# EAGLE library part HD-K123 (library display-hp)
LED DISPLAY 2 x 1 character 7 segment, decimal points right
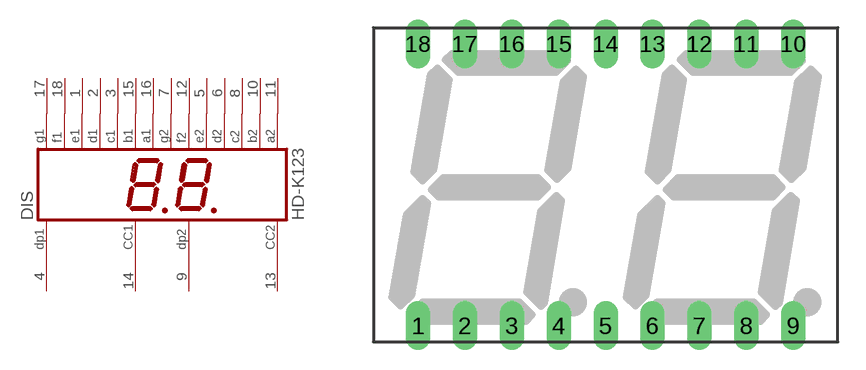
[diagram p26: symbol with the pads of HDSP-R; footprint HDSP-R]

Designator prefix DIS

## HD-K123 (OC_FARNELL: unknown; OC_NEWARK: unknown)  [HDSP-R]
1  E1  pas
2  D1  pas
3  C1  pas
4  DP1  pas
5  E2  pas
6  D2  pas
7  G2  pas
8  C2  pas
9  DP2  pas
10  B2  pas
11  A2  pas
12  F2  pas
13  CC2  pas
14  CC1  pas
15  B1  pas
16  A1  pas
17  G1  pas
18  F1  pas

## Footprint HDSP-R (pad centres in mm)
LED DISPLAY 15-mm 2 character 7 segment, decimal point right
drill 0.813 long: 1 -10.16,-7.62; 2 -7.62,-7.62; 3 -5.08,-7.62; 4 -2.54,-7.62; 5 0,-7.62; 6 2.54,-7.62; 7 5.08,-7.62; 8 7.62,-7.62; 9 10.16,-7.62; 10 10.16,7.62; 11 7.62,7.62; 12 5.08,7.62; 13 2.54,7.62; 14 0,7.62; 15 -2.54,7.62; 16 -5.08,7.62; 17 -7.62,7.62; 18 -10.16,7.62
